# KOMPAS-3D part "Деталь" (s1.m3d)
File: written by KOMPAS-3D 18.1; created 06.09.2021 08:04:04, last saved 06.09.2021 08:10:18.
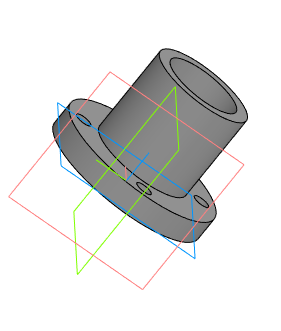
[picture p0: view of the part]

Document properties: Автор: 111; Полное имя файла: C:\Users\admin\Desktop\ffb\s1.m3d

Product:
- Part/product: Деталь
    Масса: 0.198381

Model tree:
1. Эскиз:1
2. Элемент выдавливания:1
     Расстояние 1 = 8
3. Эскиз:2  (with: Элемент выдавливания:1)
4. Элемент выдавливания:2
     Расстояние 1 = 30
5. Эскиз:3  (with: Элемент выдавливания:2)
6. Элемент выдавливания:3
     Расстояние 2 = 38
7. Эскиз:4  (with: Элемент выдавливания:1)
8. Элемент выдавливания:4
     Расстояние 2 = 8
